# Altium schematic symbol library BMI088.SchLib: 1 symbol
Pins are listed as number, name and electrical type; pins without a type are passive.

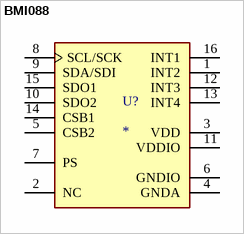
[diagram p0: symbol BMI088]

## BMI088
designator U?
High-performance 6-axis inertial sensor (accelerometer + gyroscope) <a href="https://pricing.snapeda.com/parts/BMI088/Bosch%20Sensortec/view-part?ref=eda">Check prices</a>; MP: BMI088
footprint PQFN50P450X300X100-16N
pins: 1 INT2, 2 NC, 3 VDD, 4 GNDA, 5 CSB2, 6 GNDIO, 7 PS, 8 SCL/SCK, 9 SDA/SDI, 10 SDO2, 11 VDDIO, 12 INT3, 13 INT4, 14 CSB1, 15 SDO1, 16 INT1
